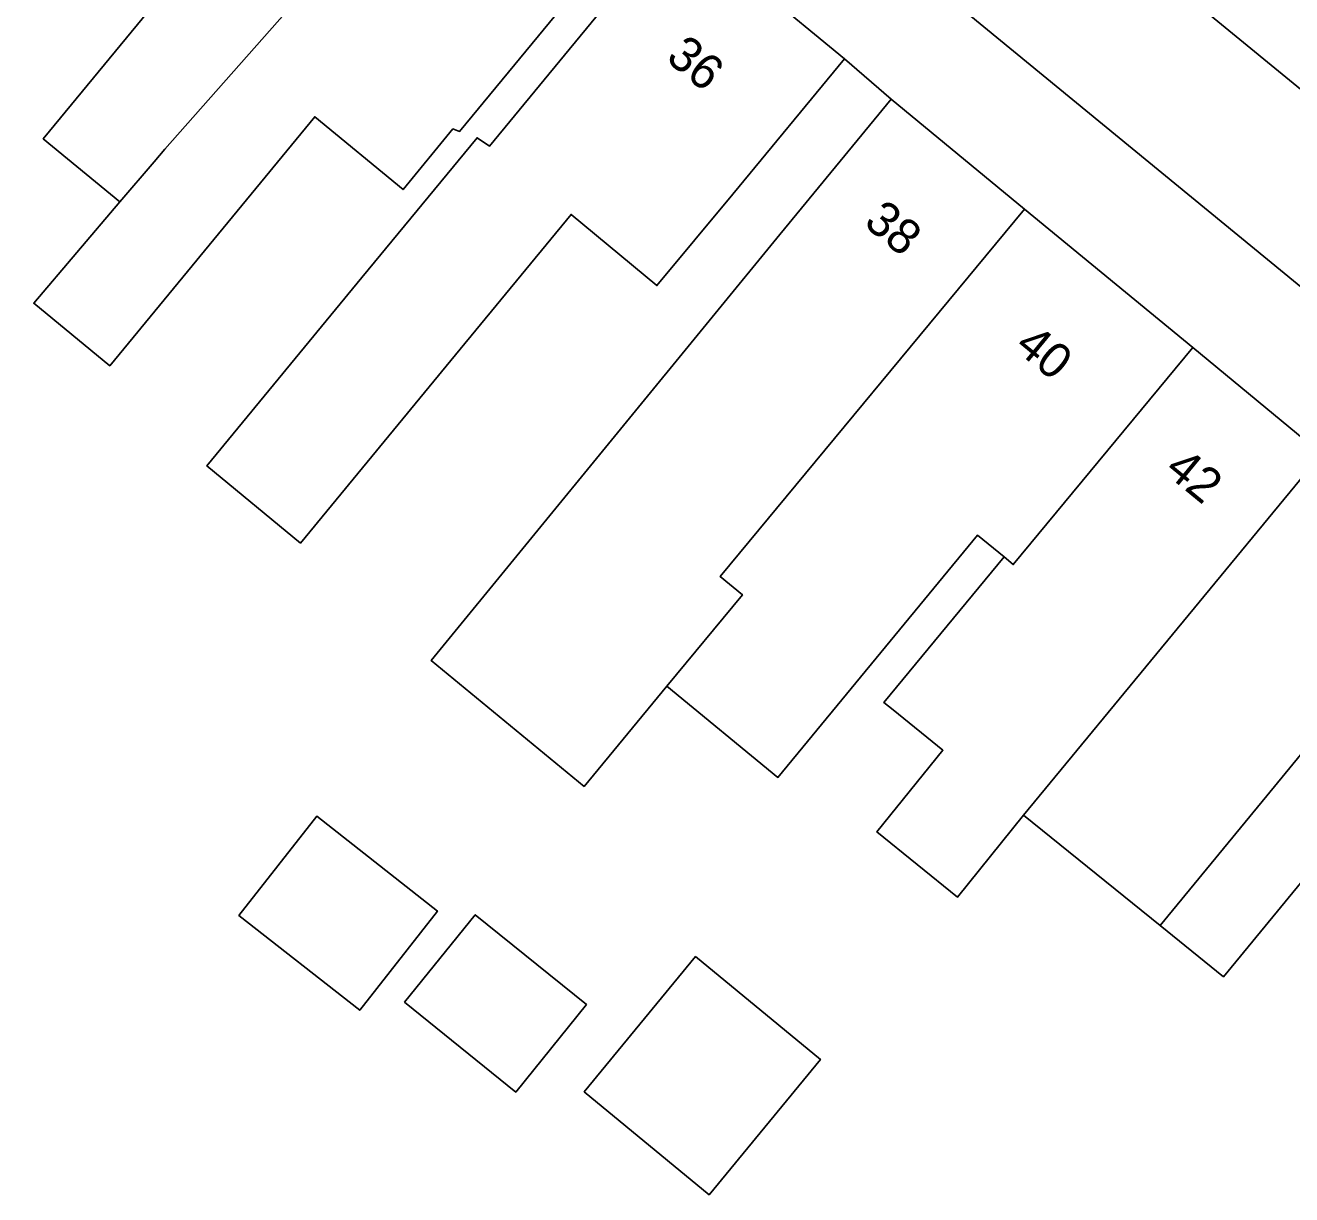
# Model space of a CAD drawing. Extents: x 160157 to 160921, y 381516 to 382045.
# Drawn here: x 160415.11 to 160451.23, y 381815.33 to 381848.68 of the extents above; entities that cross this region are included whole.
import ezdxf

# ---------------------------------------------------------------- set-up
doc = ezdxf.new("R2010")
doc.units = 0
for name, color, linetype in [('IMGEO_Erf', 7, 'Continuous'), ('IMGEO_Pand', 7, 'Continuous'), ('IMGEO_Pand_nummerreeks', 7, 'Continuous'), ('IMGEO_Parkeervlak_open', 7, 'Continuous'), ('IMGEO_Rijbaan_lokaal_open', 7, 'Continuous'), ('IMGEO_Voetpad_open', 7, 'Continuous')]:
    doc.layers.add(name, color=color, linetype=linetype)

msp = doc.modelspace()

# ---------------------------------------------------------------- linework, layer by layer
at = {"layer": 'IMGEO_Erf'}
for points in [[(160432.919, 381852.243), (160429.741, 381848.384), (160427.494, 381845.657), (160427.305, 381845.727), (160425.881, 381843.998), (160423.363, 381846.072), (160420.879, 381843.056), (160417.514, 381838.971), (160415.348, 381840.755), (160417.805, 381843.643), (160415.616, 381845.446), (160420.503, 381851.38)], [(160452.667, 381825.655), (160449.283, 381821.546), (160447.474, 381823.007), (160443.582, 381826.149), (160441.698, 381823.816), (160439.398, 381825.673), (160441.282, 381828.006), (160439.859, 381829.155), (160439.599, 381829.365), (160443.023, 381833.517), (160442.267, 381834.14), (160438.531, 381829.605), (160436.572, 381827.228), (160433.408, 381829.834), (160431.044, 381826.971), (160426.678, 381830.568), (160434.7, 381840.359), (160436.628, 381842.712), (160439.806, 381846.571), (160438.469, 381847.727), (160435.291, 381843.868), (160433.124, 381841.258), (160430.673, 381843.287), (160427.377, 381839.286), (160422.952, 381833.915), (160420.284, 381836.112), (160424.708, 381841.484), (160427.993, 381845.473), (160428.343, 381845.231), (160430.485, 381847.827), (160433.663, 381851.686)]]:
    msp.add_lwpolyline(points, dxfattribs=at)
for points in [[(160421.2, 381823.294), (160423.417, 381826.12), (160426.863, 381823.417), (160424.646, 381820.591)], [(160425.923, 381820.82), (160427.94, 381823.315), (160431.112, 381820.752), (160429.095, 381818.256)], [(160434.226, 381822.122), (160437.788, 381819.188), (160434.61, 381815.329), (160431.048, 381818.263)]]:
    msp.add_lwpolyline(points, close=True, dxfattribs=at)
at = {"layer": 'IMGEO_Pand'}
for points in [[(160428.309, 381856.04), (160423.698, 381859.838), (160420.52, 381855.979), (160418.274, 381853.247), (160420.503, 381851.38), (160415.616, 381845.446), (160417.805, 381843.643), (160418.778, 381844.786), (160419.088, 381845.146), (160422.73, 381849.268)], [(160429.741, 381848.384), (160432.919, 381852.243), (160428.309, 381856.04), (160422.73, 381849.268), (160419.088, 381845.146), (160418.778, 381844.786), (160417.805, 381843.643), (160415.348, 381840.755), (160417.514, 381838.971), (160420.879, 381843.056), (160423.363, 381846.072), (160425.881, 381843.998), (160427.305, 381845.727), (160427.494, 381845.657)], [(160433.663, 381851.686), (160430.485, 381847.827), (160428.343, 381845.231), (160427.993, 381845.473), (160424.708, 381841.484), (160420.284, 381836.112), (160422.952, 381833.915), (160427.377, 381839.286), (160430.673, 381843.287), (160433.124, 381841.258), (160435.291, 381843.868), (160438.469, 381847.727)], [(160443.609, 381843.437), (160439.806, 381846.571), (160436.628, 381842.712), (160434.7, 381840.359), (160426.678, 381830.568), (160431.044, 381826.971), (160433.408, 381829.834), (160435.561, 381832.441), (160434.93, 381832.96)], [(160448.406, 381839.488), (160443.609, 381843.437), (160434.93, 381832.96), (160435.561, 381832.441), (160433.408, 381829.834), (160436.572, 381827.228), (160438.531, 381829.605), (160442.267, 381834.14), (160443.023, 381833.517), (160443.287, 381833.299)], [(160452.077, 381836.463), (160448.406, 381839.488), (160443.287, 381833.299), (160443.023, 381833.517), (160439.599, 381829.365), (160439.859, 381829.155), (160441.282, 381828.006), (160439.398, 381825.673), (160441.698, 381823.816), (160443.582, 381826.149)], [(160447.474, 381823.007), (160450.737, 381826.969), (160455.926, 381833.293), (160452.077, 381836.463), (160443.582, 381826.149)], [(160452.667, 381825.655), (160454.63, 381824.057), (160456.536, 381826.314), (160459.714, 381830.173), (160455.926, 381833.293), (160450.737, 381826.969), (160447.474, 381823.007), (160449.283, 381821.546)], [(160423.417, 381826.12), (160421.2, 381823.294), (160424.646, 381820.591), (160426.863, 381823.417)], [(160431.112, 381820.752), (160427.94, 381823.315), (160425.923, 381820.82), (160429.095, 381818.256)], [(160437.788, 381819.188), (160434.226, 381822.122), (160431.048, 381818.263), (160434.61, 381815.329)]]:
    msp.add_lwpolyline(points, close=True, dxfattribs=at)
at = {"layer": 'IMGEO_Parkeervlak_open'}
msp.add_lwpolyline([(160460.774, 381845.714), (160459.954, 381846.377), (160451.861, 381852.989), (160448.706, 381849.132), (160474.266, 381828.22)], dxfattribs=at)
at = {"layer": 'IMGEO_Rijbaan_lokaal_open'}
for points in [[(160371.41, 381914.519), (160389.742, 381899.391), (160409.362, 381883.2), (160421.079, 381873.531), (160420.73, 381873.107), (160425.014, 381863.084), (160439.434, 381851.118), (160468.894, 381826.952), (160479.902, 381818.437)], [(160476.974, 381825.958), (160475.803, 381827.039), (160474.266, 381828.22), (160448.706, 381849.132), (160447.149, 381850.406), (160434.38, 381860.853), (160429.948, 381864.485)]]:
    msp.add_lwpolyline(points, dxfattribs=at)
at = {"layer": 'IMGEO_Voetpad_open'}
for points in [[(160479.902, 381818.437), (160468.894, 381826.952), (160439.434, 381851.118), (160425.014, 381863.084), (160420.73, 381873.107)], [(160414.72, 381867.351), (160416.323, 381866.023), (160416.785, 381865.642), (160417.041, 381865.431), (160421.277, 381861.942), (160423.698, 381859.838), (160428.309, 381856.04), (160432.919, 381852.243), (160433.663, 381851.686), (160438.469, 381847.727), (160439.806, 381846.571), (160443.609, 381843.437), (160448.406, 381839.488), (160452.077, 381836.463)]]:
    msp.add_lwpolyline(points, dxfattribs=at)

# ---------------------------------------------------------------- texts
at = {"layer": 'IMGEO_Pand_nummerreeks'}
for s, rotation, p in [('36', 320.5196, (160433.343, 381847.7)), ('38', 320.5085, (160438.986, 381842.997)), ('40', 320.5347, (160443.287, 381839.454)), ('42', 320.5232, (160447.565, 381835.931))]:
    msp.add_text(s, height=1, rotation=rotation, dxfattribs=at).set_placement(p)

doc.saveas('drawing.dxf')
